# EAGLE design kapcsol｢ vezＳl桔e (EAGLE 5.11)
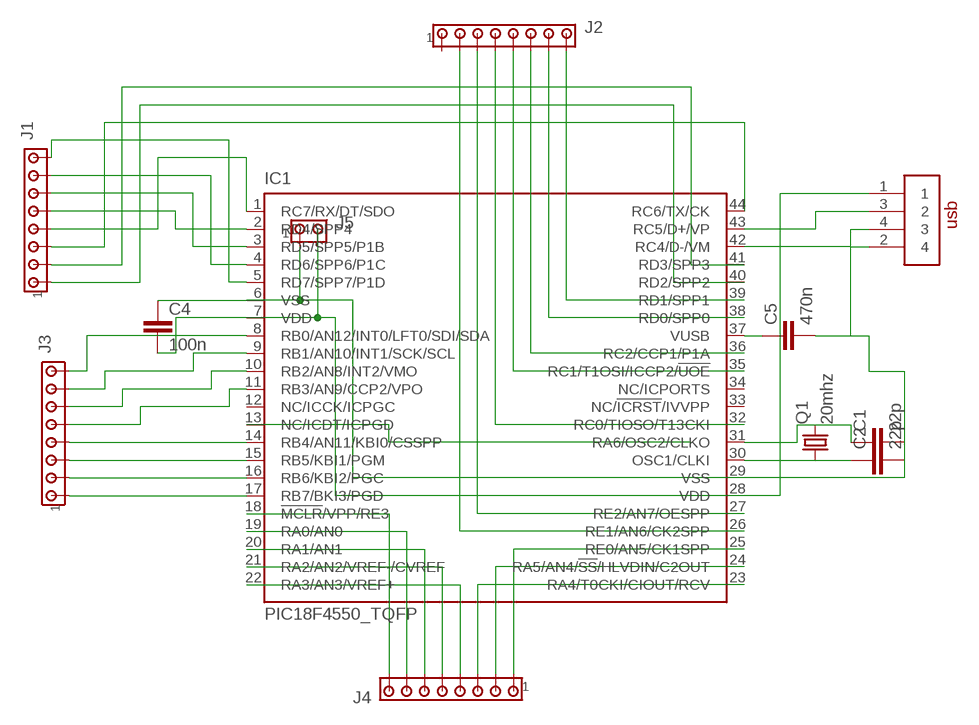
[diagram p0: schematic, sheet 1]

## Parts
C1  22p  C-EUC1206  [C1206]
C2  22p  C-EUC1206  [C1206]
C4  100n  C-EUC1206  [C1206]
C5  470n  C-EUC1206  [C1206]
IC1  PIC18F4550_TQFP  [TQFP44]
J1  MTA08-100  [10X08MTA]
J2  MTA08-100  [10X08MTA]
J3  MTA08-100  [10X08MTA]
J4  MTA08-100  [10X08MTA]
J5  MTA02-156  [1X2MTA]
Q1  20mhz  CRYSTALHC49UP  [HC49UP]
X1  USB  [USB]

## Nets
N$1: C2.1 IC1.30(OSC1/CLKI) Q1.1
N$2: IC1.14(RB4/AN11/KBI0/CSSPP) J3.4
N$3: C1.2 C2.2 C4.1 C5.2 IC1.6(VSS) IC1.29(VSS) J5.1 X1.4
N$4: C4.2 IC1.7(VDD) IC1.28(VDD) J5.2 X1.1
N$5: IC1.42(RC4/D-/VM) X1.2
N$6: IC1.43(RC5/D+/VP) X1.3
N$7: IC1.15(RB5/KBI1/PGM) J3.3
N$8: IC1.16(RB6/KBI2/PGC) J3.2
N$9: IC1.8(RB0/AN12/INT0/LFT0/SDI/SDA) J3.8
N$10: IC1.9(RB1/AN10/INT1/SCK/SCL) J3.7
N$11: IC1.10(RB2/AN8/INT2/VMO) J3.6
N$12: IC1.11(RB3/AN9/CCP2/VPO) J3.5
N$13: IC1.17(RB7/BKI3/PGD) J3.1
N$14: IC1.18(!MCLR!/VPP/RE3) J4.8
N$15: IC1.19(RA0/AN0) J4.7
N$17: IC1.21(RA2/AN2/VREF-/CVREF) J4.5
N$18: IC1.22(RA3/AN3/VREF+) J4.4
N$19: IC1.23(RA4/T0CKI/CIOUT/RCV) J4.3
N$20: IC1.24(RA5/AN4/!SS!/HLVDIN/C2OUT) J4.2
N$21: C5.1 IC1.37(VUSB)
N$22: IC1.25(RE0/AN5/CK1SPP) J4.1
N$23: C1.1 IC1.31(RA6/OSC2/CLKO) Q1.2
N$24: IC1.5(RD7/SPP7/P1D) J1.8
N$25: IC1.4(RD6/SPP6/P1C) J1.7
N$26: IC1.3(RD5/SPP5/P1B) J1.6
N$27: IC1.2(RD4/SPP4) J1.5
N$28: IC1.1(RC7/RX/DT/SDO) J1.4
N$29: IC1.44(RC6/TX/CK) J1.3
N$30: IC1.41(RD3/SPP3) J1.2
N$31: IC1.40(RD2/SPP2) J1.1
N$32: IC1.39(RD1/SPP1) J2.8
N$33: IC1.38(RD0/SPP0) J2.7
N$34: IC1.20(RA1/AN1) J4.6
N$35: IC1.36(RC2/CCP1/P1A) J2.6
N$36: IC1.35(RC1/T1OSI/ICCP2/!UOE) J2.5
N$37: IC1.32(RC0/TIOSO/T13CKI) J2.4
N$38: IC1.27(RE2/AN7/OESPP) J2.3
N$39: IC1.26(RE1/AN6/CK2SPP) J2.2
N$40: IC1.13(NC/ICDT/ICPGD)
Unconnected: IC1.12(NC/ICCK/ICPGC) IC1.33(NC/!ICRST!/IVVPP) IC1.34(NC/ICPORTS) J2.1

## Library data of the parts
C1 C2 C4 C5 = rcl:C-EU: CAPACITOR, European symbol
IC1 = microchip:PIC18F4*_TQFP: USB Microcontrollers with nanoWatt Technology High-Performance, Enhanced Flash, 28/40/44-Pin, Source: http://ww1.microchip.com/downloads/en/devicedoc/39632c.pdf; MF: MICROCHIP; MPN: PIC18F4550-I/PT; OC_FARNELL: 9321365; OC_NEWARK: 08J9633
J1-J4 = con-amp:MTA08-100: AMP connector; OC_FARNELL: unknown; OC_NEWARK: unknown
J5 = con-amp:MTA02-156: AMP connector; OC_FARNELL: unknown; OC_NEWARK: unknown
Q1 = crystal:CRYSTAL: CRYSTAL; OC_FARNELL: unknown; OC_NEWARK: unknown
X1 = usb:USB

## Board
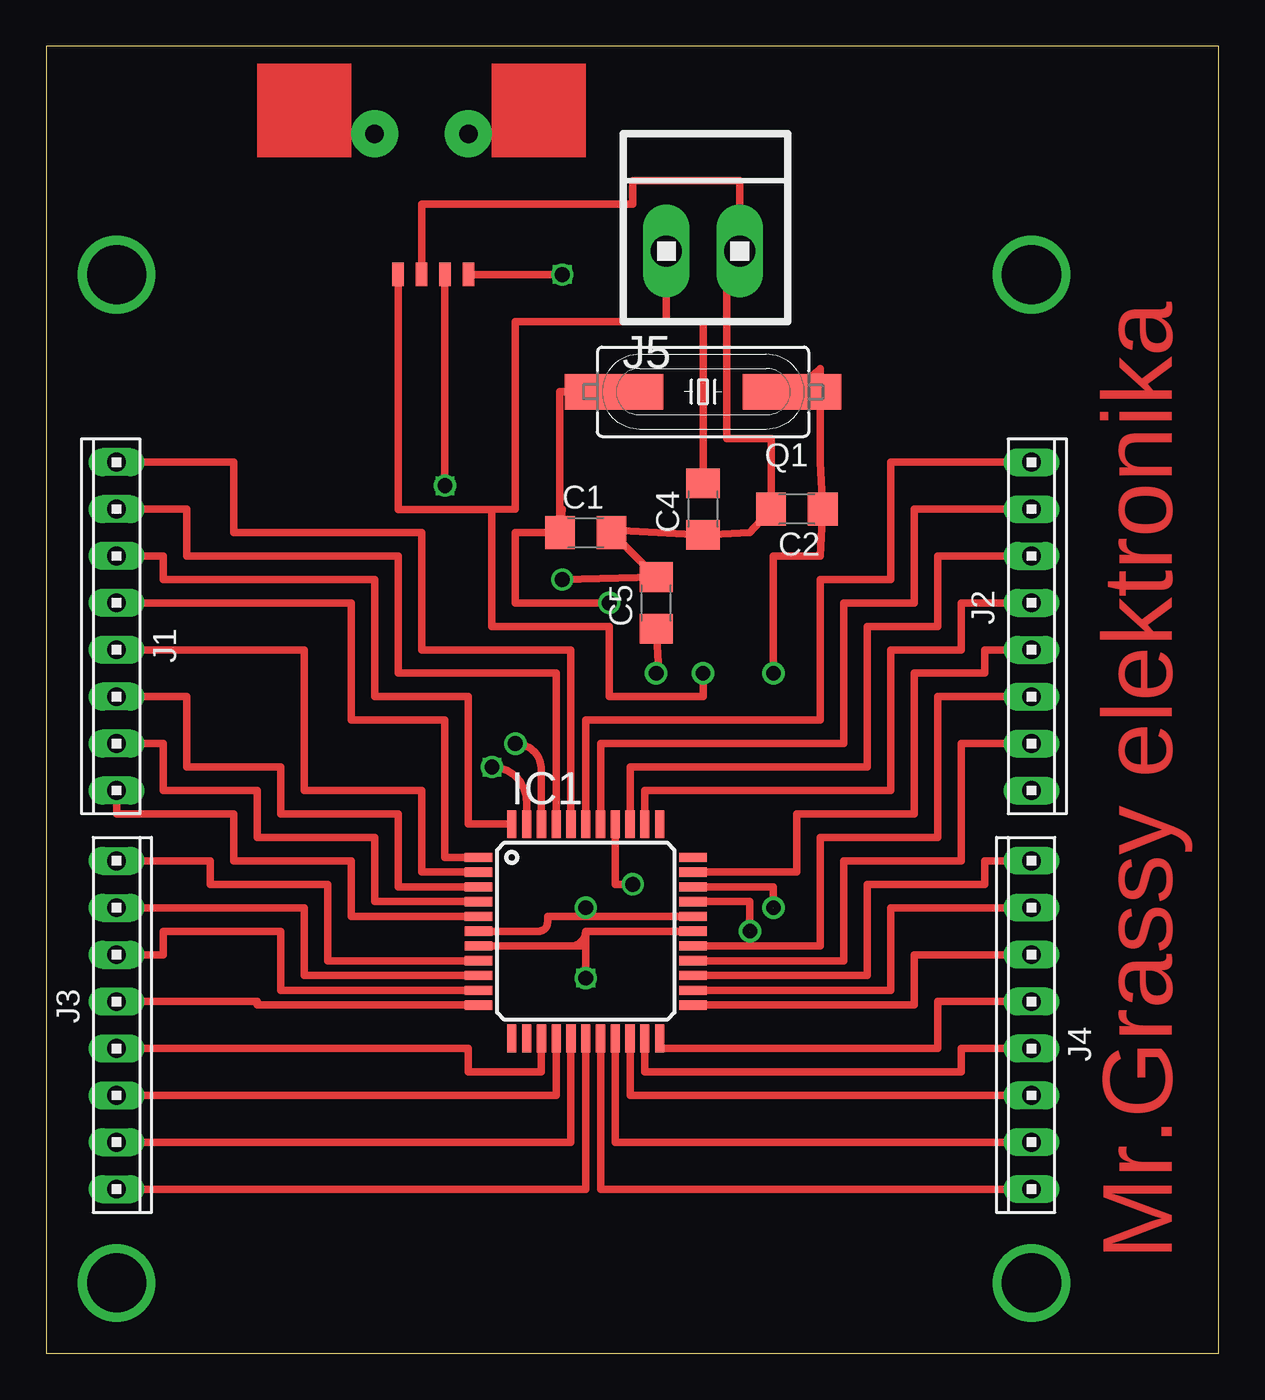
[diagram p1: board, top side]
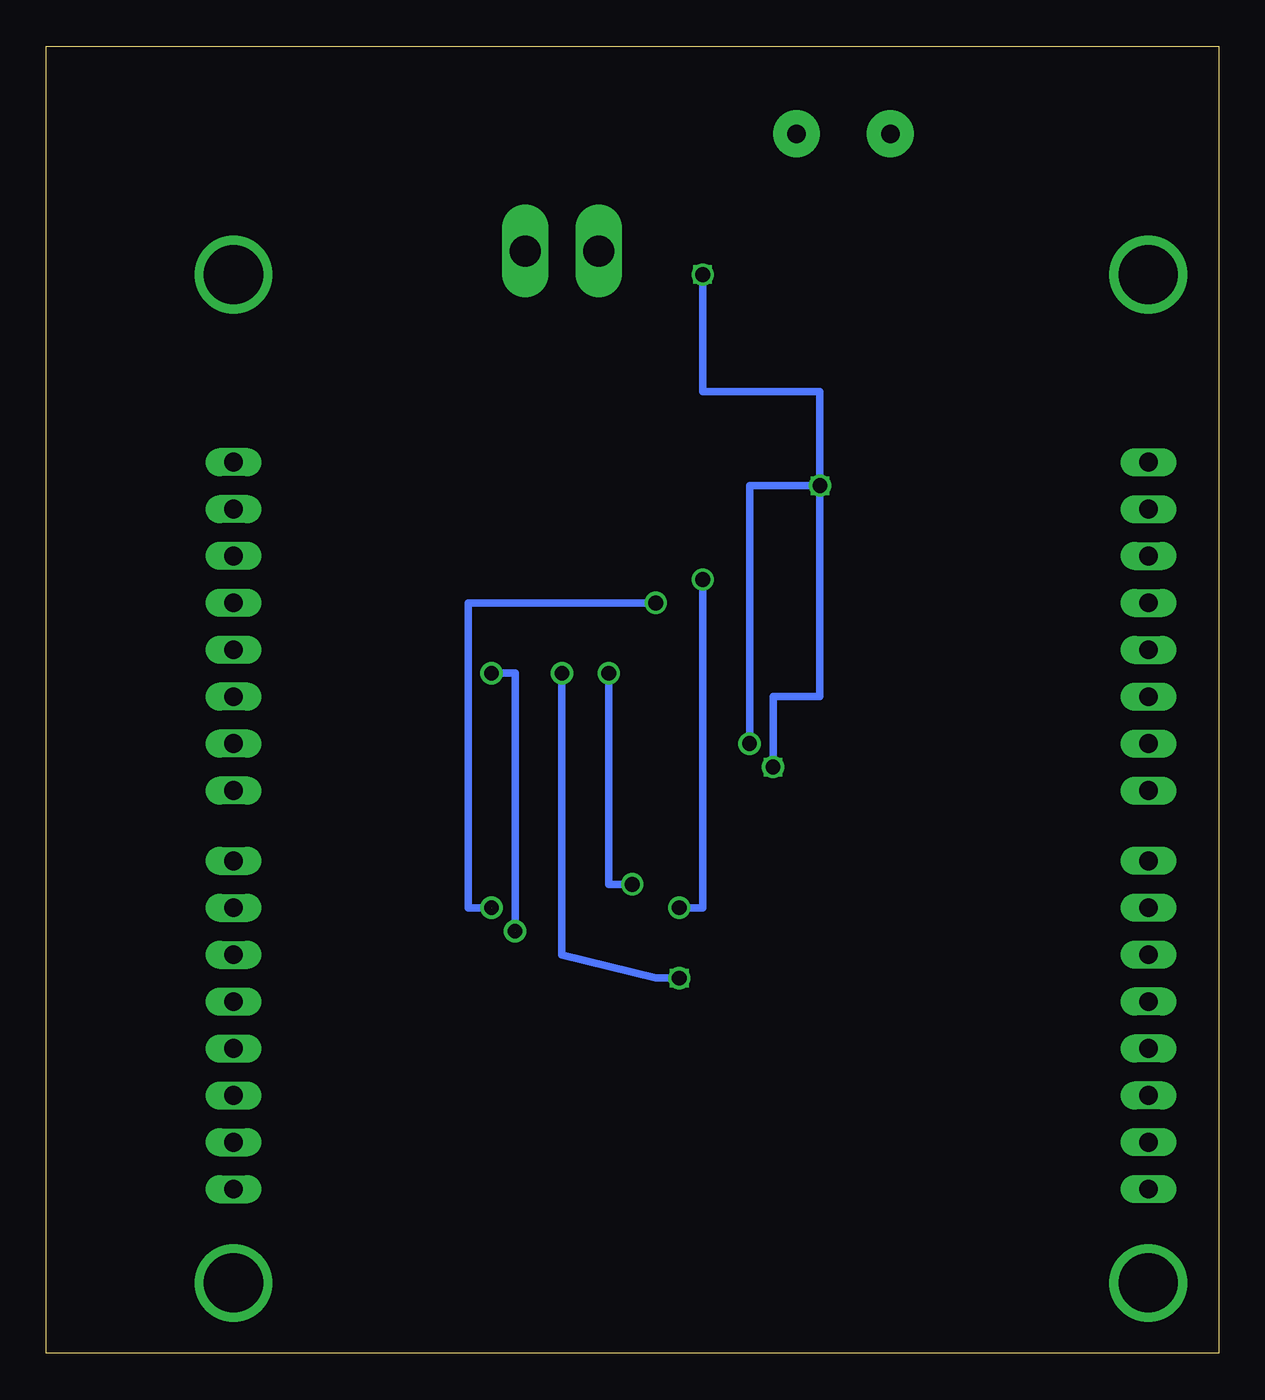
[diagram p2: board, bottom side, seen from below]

Size 63.48 x 70.79 mm. Coordinates in mm from the lower left corner, seen from the top.
Outline: 0,0 63.48,0 63.48,70.79 0,70.79 0,0
Copper layers (1*16): Top 0.035mm / dielectric 1.5mm / Bottom 0.035mm
Design rules "default": minimum track width 10mil, minimum drill 24mil, track to track 8mil, track to pad 8mil, pad to pad 8mil, via to via 8mil, smd to smd 8mil, copper to edge 40mil, drill to drill 8mil, minimum pad ring 10mil, minimum via ring 8mil, stop-mask expansion 4mil, vias tented up to drill 0mil, thermal gap 10mil

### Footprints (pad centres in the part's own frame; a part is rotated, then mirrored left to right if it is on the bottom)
C1206 = smd 1.6 x 1.8: 1 -1.4,0; 2 1.4,0
TQFP44 = smd 1.5 x 0.5: 1 -5.8,4; 2 -5.8,3.2; 3 -5.8,2.4; 4 -5.8,1.6; 5 -5.8,0.8; 6 -5.8,0; 7 -5.8,-0.8; 8 -5.8,-1.6; 9 -5.8,-2.4; 10 -5.8,-3.2; 11 -5.8,-4; 23 5.8,-4; 24 5.8,-3.2; 25 5.8,-2.4; 26 5.8,-1.6; 27 5.8,-0.8; 28 5.8,0; 29 5.8,0.8; 30 5.8,1.6; 31 5.8,2.4; 32 5.8,3.2; 33 5.8,4 | smd 0.5 x 1.5: 12 -4,-5.8; 13 -3.2,-5.8; 14 -2.4,-5.8; 15 -1.6,-5.8; 16 -0.8,-5.8; 17 0,-5.8; 18 0.8,-5.8; 19 1.6,-5.8; 20 2.4,-5.8; 21 3.2,-5.8; 22 4,-5.8; 34 4,5.8; 35 3.2,5.8; 36 2.4,5.8; 37 1.6,5.8; 38 0.8,5.8; 39 0,5.8; 40 -0.8,5.8; 41 -1.6,5.8; 42 -2.4,5.8; 43 -3.2,5.8; 44 -4,5.8
10X08MTA = drill 1.016 long: 1 8.89,0; 2 6.35,0; 3 3.81,0; 4 1.27,0; 5 -1.27,0; 6 -3.81,0; 7 -6.35,0; 8 -8.89,0
1X2MTA = drill 1.676 long: 1 1.981,0; 2 -1.981,0
HC49UP = smd 5.334 x 1.93: 1 -4.826,0; 2 4.826,0
USB = smd 1.27 x 0.635: 1 -7.62,2.54; 2 -7.62,0; 3 -7.62,-1.27; 4 -7.62,1.27

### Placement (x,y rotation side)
C1  29.21,44.45 0 top
C2  40.64,45.72 180 top
C4  35.56,45.72 90 top
C5  33.02,40.64 90 top
IC1  29.21,22.86 0 top
J1  3.81,39.37 90 top
J2  53.34,39.37 270 top
J3  3.81,17.78 270 top
J4  53.34,17.78 90 top
J5  35.56,59.69 0 top
Q1  35.56,52.07 180 top
X1  21.59,66.04 90 top

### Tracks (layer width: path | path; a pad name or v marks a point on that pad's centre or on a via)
N$1  (via drill 0.8)  (1 unrouted)
  Top 0.406: IC1.30 38.1,24.46 38.1,22.86 | Q1.1 41.91,53.34 41.91,48.26 C2.1 41.91,43.18 39.37,43.18 v39.37,36.83
  Bottom 0.406: v39.37,36.83 38.1,36.83 38.1,22.86
N$2
  Top 0.406: J3.4 22.86,16.51 22.86,15.24 26.81,15.24 IC1.14
N$3  (via drill 0.8)
  Top 0.406: IC1.6 26.67,22.86 arc90 27.14,23.33 27.14,23.66 IC1.29 29.21,23.66 v29.21,24.13 | v27.94,41.91 C5.2 C1.2 30.61,44.58 C4.1 38.1,44.45 C2.2 39.24,49.53 36.83,49.53 36.83,60.96 J5.1 37.54,63.5 31.75,63.5 31.75,62.23 20.32,62.23 X1.4
  Bottom 0.406: v29.21,24.13 27.94,24.13 v27.94,41.91
N$4  (via drill 0.6, 0.8)
  Top 0.406: 29.21,22.86 arc-90 28.41,22.06 | 29.21,22.86 IC1.28 | 24.13,45.69 19.05,45.69 X1.1 | 33.58,55.88 25.4,55.88 25.4,45.72 24.13,45.69 | 33.58,55.88 J5.2 | C4.2 35.56,55.88 33.58,55.88 | 24.13,45.69 24.13,39.37 30.48,39.37 30.48,35.56 35.56,35.56 v35.56,36.83 | 29.21,22.06 29.21,21.59 v29.21,20.32 | IC1.7 29.21,22.06 | 29.21,22.06 29.21,22.86
  Bottom 0.406: v35.56,36.83 35.56,21.59 30.48,20.32 v29.21,20.32
N$5  (via drill 0.6)
  Top 0.406: 26.81,31.61 arc90 25.4,33.02 arc-90 26.81,31.61 | v21.59,46.99 X1.2 | IC1.42 26.81,31.61
  Bottom 0.406: v21.59,46.99 25.4,46.99 25.4,33.02
N$6  (via drill 0.6)
  Top 0.406: 26.01,29.87 arc90 v24.13,31.75 arc-90 26.01,29.87 | v27.94,58.42 X1.3 | IC1.43 26.01,29.87
  Bottom 0.406: v27.94,58.42 27.94,52.07 21.59,52.07 21.59,35.56 24.13,35.56 v24.13,31.75
N$7
  Top 0.406: J3.3 27.61,13.97 IC1.15
N$8
  Top 0.406: J3.2 28.41,11.43 IC1.16
N$9
  Top 0.406: IC1.8 15.24,21.26 15.24,25.4 8.89,25.4 8.89,26.67 J3.8
N$10
  Top 0.406: IC1.9 13.97,20.46 13.97,24.13 J3.7
N$11
  Top 0.406: IC1.10 12.7,19.66 12.7,22.86 6.35,22.86 6.35,21.59 J3.6
N$12
  Top 0.406: IC1.11 11.43,18.86 11.43,19.05 J3.5
N$13
  Top 0.406: J3.1 29.21,8.89 IC1.17
N$14
  Top 0.406: J4.8 30.01,8.89 IC1.18
N$15
  Top 0.406: J4.7 30.81,11.43 IC1.19
N$16  (via drill 0.8)
  other vias: 29.21,24.13
N$17
  Top 0.406: J4.5 49.53,16.51 49.53,15.24 32.41,15.24 IC1.21
N$18
  Top 0.406: J4.4 48.26,19.05 48.26,16.51 33.21,16.51 IC1.22
N$19
  Top 0.406: IC1.23 46.99,18.86 46.99,21.59 J4.3
N$20
  Top 0.406: IC1.24 45.72,19.66 45.72,24.13 J4.2
N$21  (via drill 0.8)
  Top 0.406: C5.1 33.15,36.96 v33.02,36.83 | v31.75,25.4 30.81,25.4 IC1.37
  Bottom 0.406: v33.02,36.83 33.02,25.4 v31.75,25.4
N$22
  Top 0.406: IC1.25 44.45,20.46 44.45,25.4 50.8,25.4 50.8,26.67 J4.1
N$23  (via drill 0.8)  (1 unrouted)
  Top 0.406: IC1.31 39.37,25.26 39.37,24.13 | Q1.2 27.81,52.07 C1.1 | C1.1 27.94,45.72 | C1.1 25.4,44.45 25.4,40.64 v30.48,40.64
  Bottom 0.406: v30.48,40.64 40.64,40.64 40.64,24.13 39.37,24.13
N$24
  Top 0.406: IC1.5 16.51,23.66 16.51,26.67 10.16,26.67 10.16,29.21 3.81,29.21 J1.8
N$25
  Top 0.406: IC1.4 17.78,24.46 17.78,27.94 11.43,27.94 11.43,30.48 6.35,30.48 6.35,33.02 J1.7
N$26
  Top 0.406: IC1.3 19.05,25.26 19.05,29.21 12.7,29.21 12.7,31.75 7.62,31.75 7.62,35.56 J1.6
N$27
  Top 0.406: IC1.2 20.32,26.06 20.32,30.48 13.97,30.48 13.97,38.1 J1.5
N$28
  Top 0.406: IC1.1 21.59,26.86 21.59,34.29 16.51,34.29 16.51,40.64 J1.4
N$29
  Top 0.406: IC1.44 22.86,28.66 22.86,35.56 17.78,35.56 17.78,41.91 6.35,41.91 6.35,43.18 J1.3
N$30
  Top 0.406: J1.2 7.62,45.72 7.62,43.18 19.05,43.18 19.05,36.83 27.61,36.83 IC1.41
N$31
  Top 0.406: J1.1 10.16,48.26 10.16,44.45 20.32,44.45 20.32,38.1 28.41,38.1 IC1.40
N$32
  Top 0.406: J2.8 45.72,48.26 45.72,41.91 41.91,41.91 41.91,34.29 29.21,34.29 IC1.39
N$33
  Top 0.406: J2.7 46.99,45.72 46.99,40.64 43.18,40.64 43.18,33.02 30.01,33.02 IC1.38
N$34
  Top 0.406: J4.6 31.61,13.97 IC1.20
N$35
  Top 0.406: J2.6 48.26,43.18 48.26,39.37 44.45,39.37 44.45,31.75 31.61,31.75 IC1.36
N$36
  Top 0.406: J2.5 49.53,40.64 49.53,38.1 45.72,38.1 45.72,30.48 32.41,30.48 IC1.35
N$37
  Top 0.406: IC1.32 40.64,26.06 40.64,29.21 46.99,29.21 46.99,36.83 50.8,36.83 50.8,38.1 J2.4
N$38
  Top 0.406: IC1.27 41.91,22.06 41.91,27.94 48.26,27.94 48.26,35.56 J2.3
N$39
  Top 0.406: IC1.26 43.18,21.26 43.18,26.67 49.53,26.67 49.53,33.02 J2.2
N$41  (via drill 0.8)
  other vias: 29.21,20.32
N$42  (via drill 0.8)
  other vias: 24.13,31.75
N$43  (via drill 0.8)
  other vias: 25.4,33.02
N$44  (via drill 0.8)
  other vias: 27.94,58.42
N$45  (via drill 0.8)
  other vias: 21.59,46.99
N$46  (via drill 0.8)
  other vias: 38.1,22.86
N$47  (via drill 0.8)
  other vias: 39.37,24.13
N$48  (via drill 0.8)
  other vias: 30.48,40.64
N$49  (via drill 0.8)
  other vias: 33.02,36.83
N$50  (via drill 0.8)
  other vias: 35.56,36.83
N$51  (via drill 0.8)
  other vias: 39.37,36.83
N$52  (via drill 0.8)
  other vias: 31.75,25.4
N$53  (via drill 0.8)
  other vias: 27.94,41.91
N$54  (via drill 3.2)
  other vias: 3.81,58.42
N$55  (via drill 3.2)
  other vias: 53.34,58.42
N$56  (via drill 3.2)
  other vias: 53.34,3.81
N$57  (via drill 3.2)
  other vias: 3.81,3.81
N$58  (via drill 1 pad 2.54)
  other vias: 17.78,66.04
N$59  (via drill 1 pad 2.54)
  other vias: 22.86,66.04

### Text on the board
Top: Mr.Grassy elektronika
